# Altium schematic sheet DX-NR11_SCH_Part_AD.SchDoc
size A4
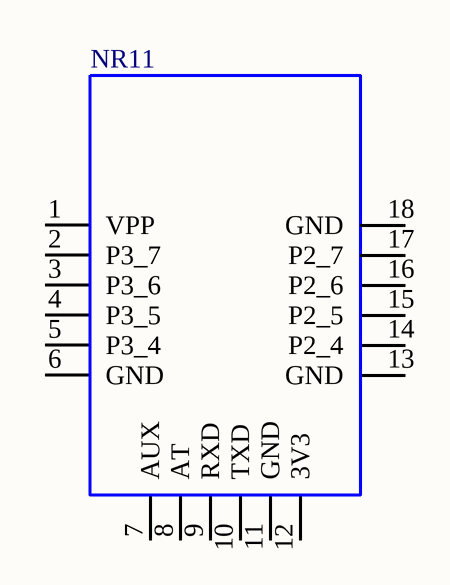
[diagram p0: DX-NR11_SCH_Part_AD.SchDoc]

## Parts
NR11  NR11  [封装]  (value not drawn)

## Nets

Not connected (* = marked no-connect by the designer): NR11 1(VPP) 2(P3_7) 3(P3_6) 4(P3_5) 5(P3_4) 6(GND) 7(AUX) 8(AT) 9(RXD) 10(TXD) 11(GND) 12(3V3) 13(GND) 14(P2_4) 15(P2_5) 16(P2_6) 17(P2_7) 18(GND)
